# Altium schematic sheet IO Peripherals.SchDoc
size A4; DocumentNumber: 6; Revision: B.2(PCB.SCH); SheetNumber: 6; SheetTotal: 6
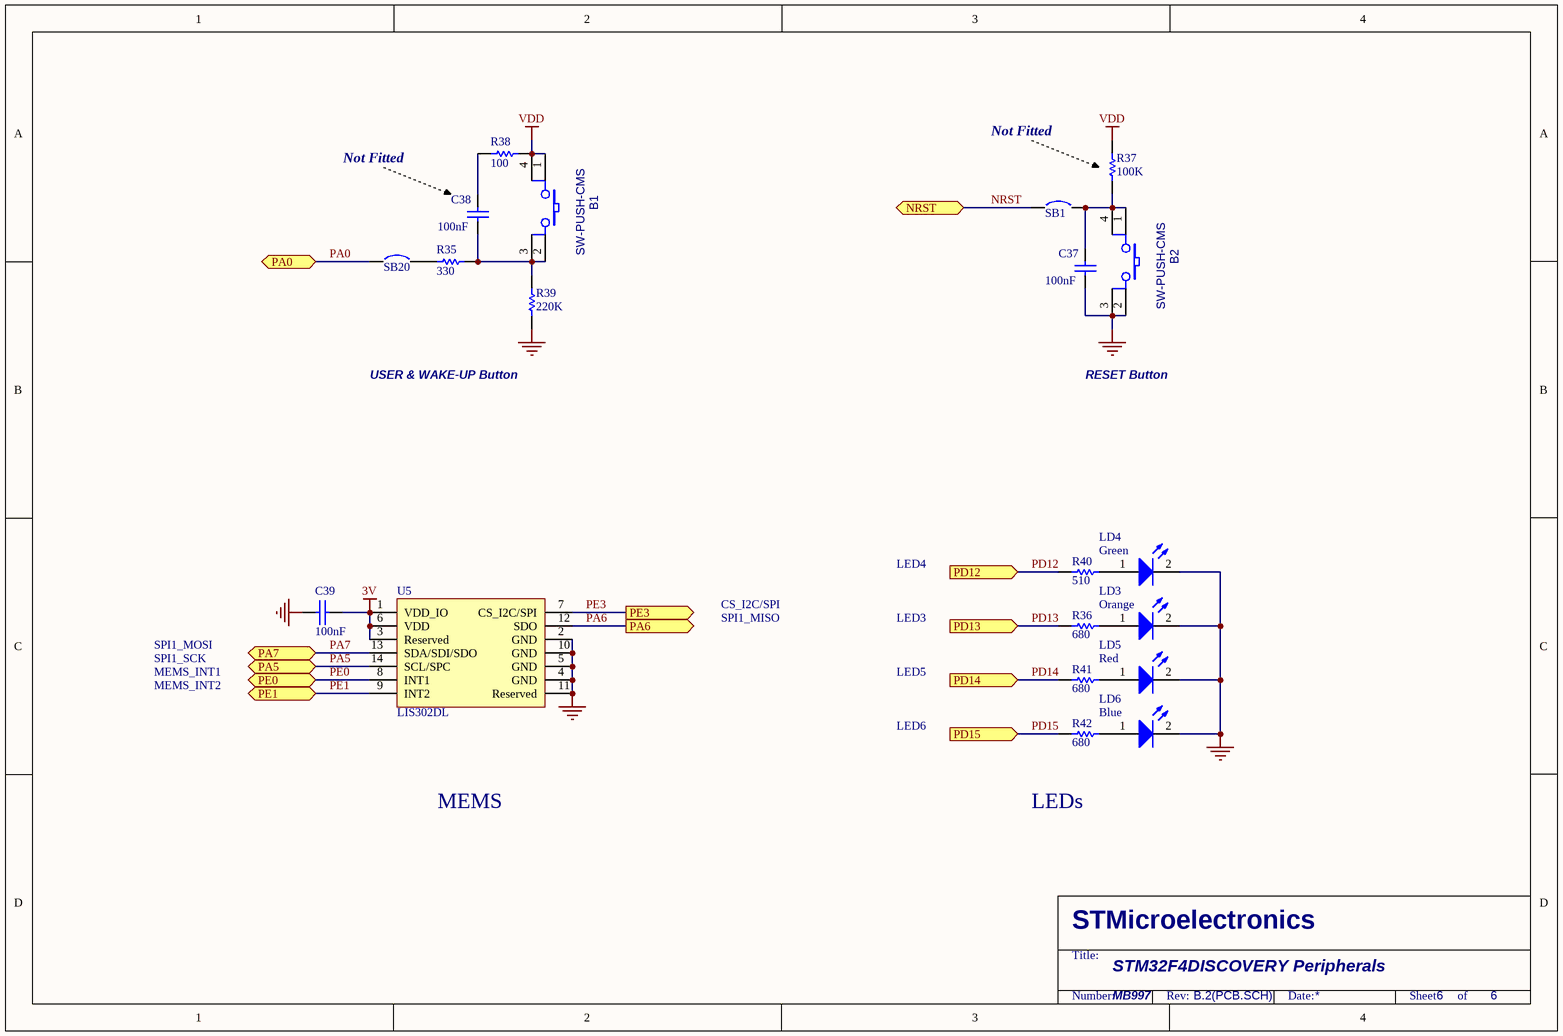
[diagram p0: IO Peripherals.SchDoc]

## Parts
B1  SW-PUSH-CMS  [BP1CMS]
B2  SW-PUSH-CMS  [BP1CMS]
C37  100nF  [0603C]
C38  100nF  [0603C]
C39  100nF  [0402C]
LD3  Orange  [0603D]
LD4  Green  [0603D]
LD5  Red  [0603D]
LD6  Blue  [0603D]
R35  330  [0402R]
R36  680  [0603R]
R37  100K  [0402R]
R38  100  [0402R]
R39  220K  [0603R]
R40  510  [0603R]
R41  680  [0603R]
R42  680  [0603R]
SB1  Circuit Breaker  [JP2_SMD]  (value not drawn)
SB20  Circuit Breaker  [JP2_SMD]  (value not drawn)
U5  LIS302DL  [LGA14(3*5)]

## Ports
NRST, PA0, PA5 (bidir), PA6 (out), PA7 (bidir), PD12 (in), PD13 (in), PD14 (in), PD15 (in), PE0, PE1, PE3 (out)

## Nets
3V: C39.2 U5.1(VDD_IO) U5.3(Reserved) U5.6(VDD)
GND: B2.2 B2.3 C37.1 C39.1 LD3.2(K) LD4.2(K) LD5.2(K) LD6.2(K) R39.1 U5.2(GND) U5.4(GND) U5.5(GND) U5.10(GND) U5.11(Reserved)
VDD: B1.1 B1.4 R37.2 R38.2
NRST: SB1.1 ; port NRST
PA0: SB20.1 ; port PA0
PA5: U5.14(SCL/SPC) ; port PA5
PA6: U5.12(SDO) ; port PA6
PA7: U5.13(SDA/SDI/SDO) ; port PA7
PD12: R40.2 ; port PD12
PD13: R36.2 ; port PD13
PD14: R41.2 ; port PD14
PD15: R42.2 ; port PD15
PE0: U5.8(INT1) ; port PE0
PE1: U5.9(INT2) ; port PE1
PE3: U5.7(CS_I2C/SPI) ; port PE3
NetB1_2: B1.2 B1.3 C38.1 R35.2 R39.2
NetB2_1: B2.1 B2.4 C37.2 R37.1 SB1.2
NetC38_2: C38.2 R38.1
NetLD3_1: LD3.1(A) R36.1
NetLD4_1: LD4.1(A) R40.1
NetLD5_1: LD5.1(A) R41.1
NetLD6_1: LD6.1(A) R42.1
NetR35_1: R35.1 SB20.2

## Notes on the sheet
- Not Fitted
- USER & WAKE-UP Button
- RESET Button
- LED4
- SPI1_MOSI
- SPI1_MISO
- CS_I2C/SPI
- LED3
- SPI1_SCK
- MEMS_INT1
- MEMS_INT2
- LED5
- LED6
- MEMS
- LEDs
- STM32F4DISCOVERY Peripherals
- MB997

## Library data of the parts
B1 B2 = SW-PUSH-CMS: Non-Open Push-Button 0.1A 24V; Manuf_1: FARNELL; Manuf_Part_1: 535-930; Ref St: 9180120; cap_dec: ---
C37 C39 = CAP: Capacitor
C38 = CAP: Capacitor; Fitted: NO
LD3-LD6 = LED2: Typical RED, GREEN, YELLOW, AMBER GaAs LED
R35 = res1: Resistor
R36 R40-R42 = Res1: Resistor; Value: 1K
R37 = res1: Resistor; Fitted: NO
R38 = res1: Resistor; Value: 330
R39 = res1: Resistor; Value: 10K
SB1 SB20 = Circuit Breaker: Solder: YES
U5 = LIS302DL: MEMS motion sensor 3-axis - ±2g/±8g smart digital output "piccolo" accelerometer; Manuf_1: STM; Manuf_Part_1: LIS302DLTR; Provided: ST; ref St: 9177944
